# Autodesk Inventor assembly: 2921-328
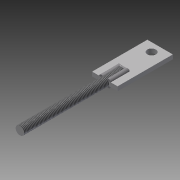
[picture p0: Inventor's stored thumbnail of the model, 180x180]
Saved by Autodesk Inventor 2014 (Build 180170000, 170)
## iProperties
Company: NHTSA/VRTC
Created: 2012-08
Part Number: 2921-328
Document SubType Name: Weldment
Designer: Mike Vanvoorhis
Weld Material: Welded Steel Mild
Mass: 296.181 g
Surface Area: 156.09 cm^2
Volume: 37.7067 cm^3
Density: 7.85488 g/cm^3
Project: CHILD SIDE IMPACT SLED
Description: D-RING LOWER ANCHOR
DESIGN DATE: 2012-11-05
Author: Dave Walker
Title: D-Ring Lower Anchor
Subject: Child Side Impact Sled
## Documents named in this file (3)
- B:\VRTC_DWG\BIO\Non-P572\Child Side-Frontal Impact Sled\Side Impact Sled\D_Ring_Anchor_Assembly1.iam
- B:\VRTC_DWG\BIO\Non-P572\Child Side-Frontal Impact Sled\Side Impact Sled\D_Ring_Anchor_Part_1.ipt
- B:\VRTC_DWG\BIO\Non-P572\Child Side-Frontal Impact Sled\Side Impact Sled\D_Ring_Anchor_Part_2.ipt
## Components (2 placed, 2 different names)
1. D_Ring_Anchor_Part_1:1 — Mate:1
2. D_Ring_Anchor_Part_2:1 — Mate:1
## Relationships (1: Mate 1)
- Mate:1: D_Ring_Anchor_Part_1:1 ↔ D_Ring_Anchor_Part_2:1
